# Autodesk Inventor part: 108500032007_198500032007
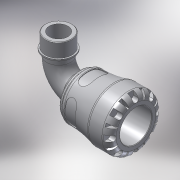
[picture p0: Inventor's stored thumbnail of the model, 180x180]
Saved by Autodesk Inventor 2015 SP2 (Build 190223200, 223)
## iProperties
Created: 2016-12
Part Number: 108500032007_198500032007
Material: PVC-Piping
Description: PLASSON 90° ELBOW WITH THREADED MALE OFFTAKE 32X3/4" SERIES 1
Document SubType Name: Modeling
Designer: KIM
Mass: 135.667 g
Surface Area: 289.954 cm^2
Volume: 96.905 cm^3
Density: 1.4 g/cm^3
Appearance: Smooth - White
Author: KIM
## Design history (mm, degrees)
derived "1085.ipt"
feature "Solid1::1085.ipt"
tag "TaggingFeature1"
body "Solid1"
other parameters: "d1" = 22.26, "d2" = 32, "d4" = 58, "d8" = 49.3, "d13" = 7.2, "d14" = 7.2, "d15" = 0, "d17" = 360 deg, "d19" = 8 deg, "d20" = 0.64, "d21" = 0.64, "d22" = 8 deg, "d24" = 0, "d26" = 360 deg, "d33" = 5.8, "d43" = 45.24, "d51" = 0.58, "d54" = 11.2, "d55" = 7.04, "d57" = 14.112, "d58" = 0, "d74" = 0, "d78" = 53, "d82" = 0.64, "d115" = 360 deg, "d207" = 90 deg, "d228" = 9.52, "d247" = 1.16, "d248" = 3.18, "d268" = 27.115, "d269" = 3.18, "d270" = 81, "d276" = 26.441, "d277" = 17, "d278" = 29.0851, "d279" = 51, "d280" = 18.7, "d281" = 3.96615, "d283" = 23.7969, "d286" = 0, "d287" = 0, "d288" = 18.5087, "d290" = 10.72155, "d292" = 30 deg, "d_" = 32, "E_" = 58, "l_" = 53, "A_" = 81, "A_1" = 51, "l_2" = 17, "R_" = 26.441, "d9" = 9, "d11" = 58, "d289" = 18.5087
